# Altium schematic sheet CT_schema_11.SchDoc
size 274 x 160 mm
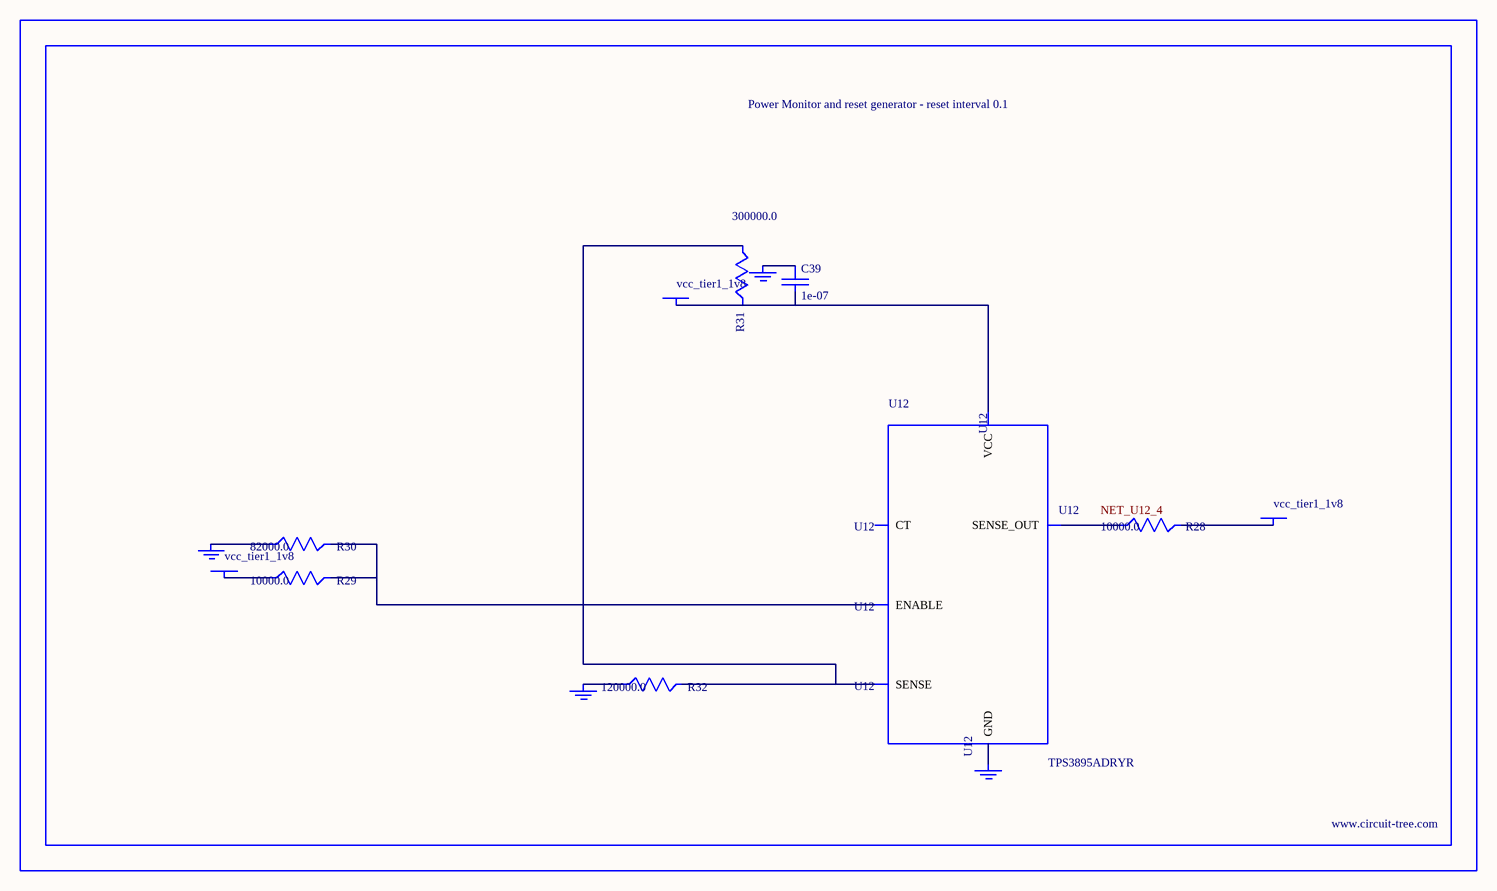
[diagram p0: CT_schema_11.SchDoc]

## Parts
BORDER10  (no value)
C39  1e-07  [C0402]
GND_INSTANCE_10_0  (no value)
GND_INSTANCE_10_1  (no value)
GND_INSTANCE_10_2  (no value)
GND_INSTANCE_10_3  (no value)
POWER_INSTANCE_10_0  vcc_tier1_1v8
POWER_INSTANCE_10_1  vcc_tier1_1v8
POWER_INSTANCE_10_2  vcc_tier1_1v8
R28  10000.0  [R0603]
R29  10000.0  [R0603]
R30  82000.0  [R0603]
R31  300000.0  [R0603]
R32  120000.0  [R0603]
U12  TPS3895ADRYR  [SON-6]

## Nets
NetC39_1: C39.1 GND_INSTANCE_10_2.0(GND)
NetC39_2: C39.2 POWER_INSTANCE_10_2.0(PWR) R31.2 U12.6(VCC)
NetGND_INSTANCE_10_0_0: GND_INSTANCE_10_0.0(GND) R30.1
NetGND_INSTANCE_10_1_0: GND_INSTANCE_10_1.0(GND) R32.1
NetGND_INSTANCE_10_3_0: GND_INSTANCE_10_3.0(GND) U12.2(GND)
NetPOWER_INSTANCE_10_0_0: POWER_INSTANCE_10_0.0(PWR) R29.1
NetPOWER_INSTANCE_10_1_0: POWER_INSTANCE_10_1.0(PWR) R28.2
NetR28_1: R28.1 U12.4(SENSE_OUT)
NetR29_2: R29.2 R30.2 U12.1(ENABLE)
NetR31_1: R31.1 R32.2 U12.3(SENSE)

Not connected (* = marked no-connect by the designer): U12 5(CT)

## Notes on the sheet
- Labels drawn without touching a wire or pin: NET_U12_4

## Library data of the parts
BORDER10 = BORDER_PAGE10
C39 = C0402C104K3RACTU
GND_INSTANCE_10_0-GND_INSTANCE_10_3 = GND
POWER_INSTANCE_10_0-POWER_INSTANCE_10_2 = PWR
R28 R29 = RC0603JR-0710KL
R30 = RC0603JR-0782KL
R31 = RC0603JR-07300KL
R32 = RC0603JR-07120KL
